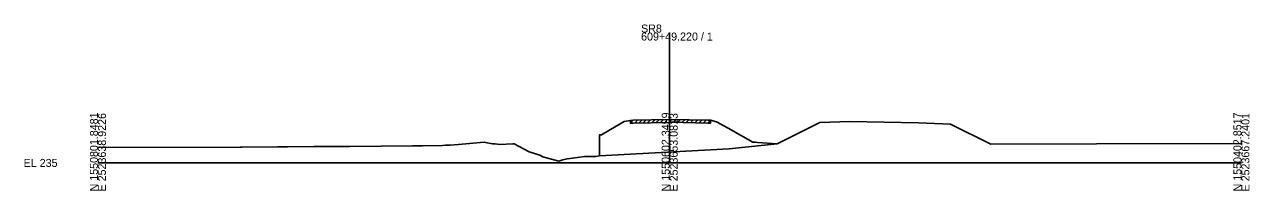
# Model space of a CAD drawing. Extents: x -26 to 2803, y -10 to 19537.
# Drawn here: x -25.7 to 402.8, y 15490.3 to 15548.6 of the extents above; entities that cross this region are included whole.
import ezdxf

# ---------------------------------------------------------------- set-up
doc = ezdxf.new("R2010")
doc.units = 0
for name, color, linetype in [('1', 7, 'Continuous'), ('Draft_XS_Grid', 7, 'Continuous'), ('Draft_XS_Text', 7, 'Continuous'), ('DTM_X_GROUND', 7, 'Continuous'), ('SLOPE_STAKES_FILL', 7, 'Continuous'), ('XS_P_SHOULDER', 7, 'Continuous')]:
    doc.layers.add(name, color=color, linetype=linetype)

msp = doc.modelspace()

# ---------------------------------------------------------------- linework, layer by layer
at = {"layer": '1'}
for p, q in [((200, 15500), (200, 15545.72)), ((0, 15500), (200, 15500)), ((200, 15500), (400, 15500))]:
    msp.add_line(p, q, dxfattribs=at)
at = {"layer": 'Draft_XS_Grid'}
for p, q in [((186.27, 15513.92), (187.29, 15514.95)), ((186.27, 15513.92), (186.27, 15514.92)), ((186.27, 15513.92), (187.19, 15513.94)), ((187.19, 15513.94), (200, 15514.23)), ((187.77, 15513.96), (188.79, 15514.98)), ((189.27, 15513.99), (190.29, 15515.01)), ((190.77, 15514.02), (191.79, 15515.05)), ((192.27, 15514.06), (193.29, 15515.08)), ((193.77, 15514.09), (194.79, 15515.11)), ((195.27, 15514.12), (196.29, 15515.15)), ((196.77, 15514.16), (197.79, 15515.18)), ((198.27, 15514.19), (199.29, 15515.22)), ((199.77, 15514.23), (200.77, 15515.23)), ((200, 15514.23), (200.33, 15514.24)), ((200.33, 15514.24), (213.35, 15513.96)), ((201.27, 15514.22), (202.25, 15515.2)), ((202.77, 15514.19), (203.75, 15515.17)), ((204.27, 15514.15), (205.25, 15515.13)), ((205.77, 15514.12), (206.75, 15515.1)), ((207.27, 15514.09), (208.25, 15515.07)), ((208.77, 15514.06), (209.75, 15515.04)), ((210.27, 15514.03), (211.25, 15515.01)), ((211.77, 15513.99), (212.75, 15514.97)), ((213.27, 15513.96), (214.25, 15514.94)), ((213.35, 15513.96), (214.32, 15513.94)), ((214.32, 15514.94), (214.32, 15513.94))]:
    msp.add_line(p, q, dxfattribs=at)
at = {"layer": 'Draft_XS_Text'}
for p, q in [((237.63, 15506.73), (252.53, 15514.15)), ((252.53, 15514.15), (263, 15514.57)), ((263, 15514.57), (275, 15514.33)), ((275, 15514.33), (287, 15514.09)), ((287, 15514.09), (298.2, 15513.64)), ((298.2, 15513.64), (312.3, 15506.61))]:
    msp.add_line(p, q, dxfattribs=at)
for points in [[(0, 15505.36), (49.77, 15505.49), (50.41, 15505.49), (62.91, 15505.59), (66.36, 15505.63), (75.47, 15505.7), (81.89, 15505.76), (88.06, 15505.81), (110.08, 15505.94), (113.49, 15505.99), (120.51, 15506.12), (121.57, 15506.19), (123.22, 15506.28), (126.16, 15506.46), (135.11, 15507.28), (135.61, 15507.18), (138.03, 15506.7), (138.91, 15506.7), (140.61, 15506.43), (145.19, 15506.68), (145.61, 15506.73), (150.8, 15503.88), (154.58, 15502.71), (155.63, 15502.16), (161.25, 15500.64), (162.66, 15501.04), (164.13, 15501.45), (165.24, 15501.54), (170.17, 15502.29), (173.85, 15502.24), (174.16, 15502.24), (175.4, 15502.5), (175.4, 15509.82), (175.75, 15509.82), (176.2, 15509.82), (181.3, 15512.84), (184.12, 15514.5), (186.27, 15514.92), (187.19, 15514.94), (200, 15515.23), (200.33, 15515.24), (213.35, 15514.96), (214.32, 15514.94), (216.41, 15514.43), (220.41, 15512.19), (229.11, 15507.32), (230.01, 15507.25), (230.75, 15507.2), (237.63, 15506.73)], [(312.3, 15506.61), (349.28, 15506.71), (400, 15506.8)]]:
    msp.add_lwpolyline(points, dxfattribs=at)
at = {"layer": 'DTM_X_GROUND'}
for p, q in [((175.4, 15502.5), (220.8, 15504.97)), ((220.8, 15504.97), (237.63, 15506.73))]:
    msp.add_line(p, q, dxfattribs=at)
at = {"layer": 'SLOPE_STAKES_FILL'}
for p, q in [((237.63, 15506.73), (252.53, 15514.15)), ((252.53, 15514.15), (263, 15514.57)), ((263, 15514.57), (275, 15514.33)), ((275, 15514.33), (287, 15514.09)), ((287, 15514.09), (298.2, 15513.64)), ((298.2, 15513.64), (312.3, 15506.61)), ((175.4, 15502.5), (220.8, 15504.97)), ((220.8, 15504.97), (237.63, 15506.73))]:
    msp.add_line(p, q, dxfattribs=at)
for points in [[(0, 15505.36), (49.77, 15505.49), (50.41, 15505.49), (62.91, 15505.59), (66.36, 15505.63), (75.47, 15505.7), (81.89, 15505.76), (88.06, 15505.81), (110.08, 15505.94), (113.49, 15505.99), (120.51, 15506.12), (121.57, 15506.19), (123.22, 15506.28), (126.16, 15506.46), (135.11, 15507.28), (135.61, 15507.18), (138.03, 15506.7), (138.91, 15506.7), (140.61, 15506.43), (145.19, 15506.68), (145.61, 15506.73), (150.8, 15503.88), (154.58, 15502.71), (155.63, 15502.16), (161.25, 15500.64), (162.66, 15501.04), (164.13, 15501.45), (165.24, 15501.54), (170.17, 15502.29), (173.85, 15502.24), (174.16, 15502.24), (175.4, 15502.5)], [(237.63, 15506.73), (237.63, 15506.73)], [(312.3, 15506.61), (349.28, 15506.71), (400, 15506.8)]]:
    msp.add_lwpolyline(points, dxfattribs=at)
at = {"layer": 'XS_P_SHOULDER'}
for points in [[(184.12, 15514.5), (186.27, 15514.92), (186.27, 15513.92), (187.19, 15513.94), (200, 15514.23), (200.33, 15514.24), (213.35, 15513.96), (214.32, 15513.94), (214.32, 15514.94), (216.41, 15514.43), (220.41, 15512.19), (229.11, 15507.32), (230.01, 15507.25), (230.75, 15507.2), (237.63, 15506.73), (220.8, 15504.97), (175.4, 15502.5), (175.4, 15509.82), (175.75, 15509.82), (176.2, 15509.82), (181.3, 15512.84)], [(200, 15514.23), (200.33, 15514.24), (213.35, 15513.96), (214.32, 15513.94), (214.32, 15514.94), (213.35, 15514.96), (200.33, 15515.24), (200, 15515.23), (187.19, 15514.94), (186.27, 15514.92), (186.27, 15513.92), (187.19, 15513.94)]]:
    msp.add_lwpolyline(points, close=True, dxfattribs=at)

# ---------------------------------------------------------------- texts
at = {"layer": '1'}
for s, p in [('SR8', (190, 15545.72)), ('609+49.220 / 1', (190, 15542.92)), ('EL 235', (-26, 15498.6))]:
    msp.add_text(s, height=2.8, dxfattribs=at).set_placement(p)
for s, p in [('N 1550801.8481', (0, 15490)), ('E 2523638.9226', (2.8, 15490)), ('N 1550602.3499', (200, 15490)), ('E 2523653.0813', (202.8, 15490)), ('N 1550402.8517', (400, 15490)), ('E 2523667.2401', (402.8, 15490))]:
    msp.add_text(s, height=2.8, rotation=90, dxfattribs=at).set_placement(p)

doc.saveas('drawing.dxf')
